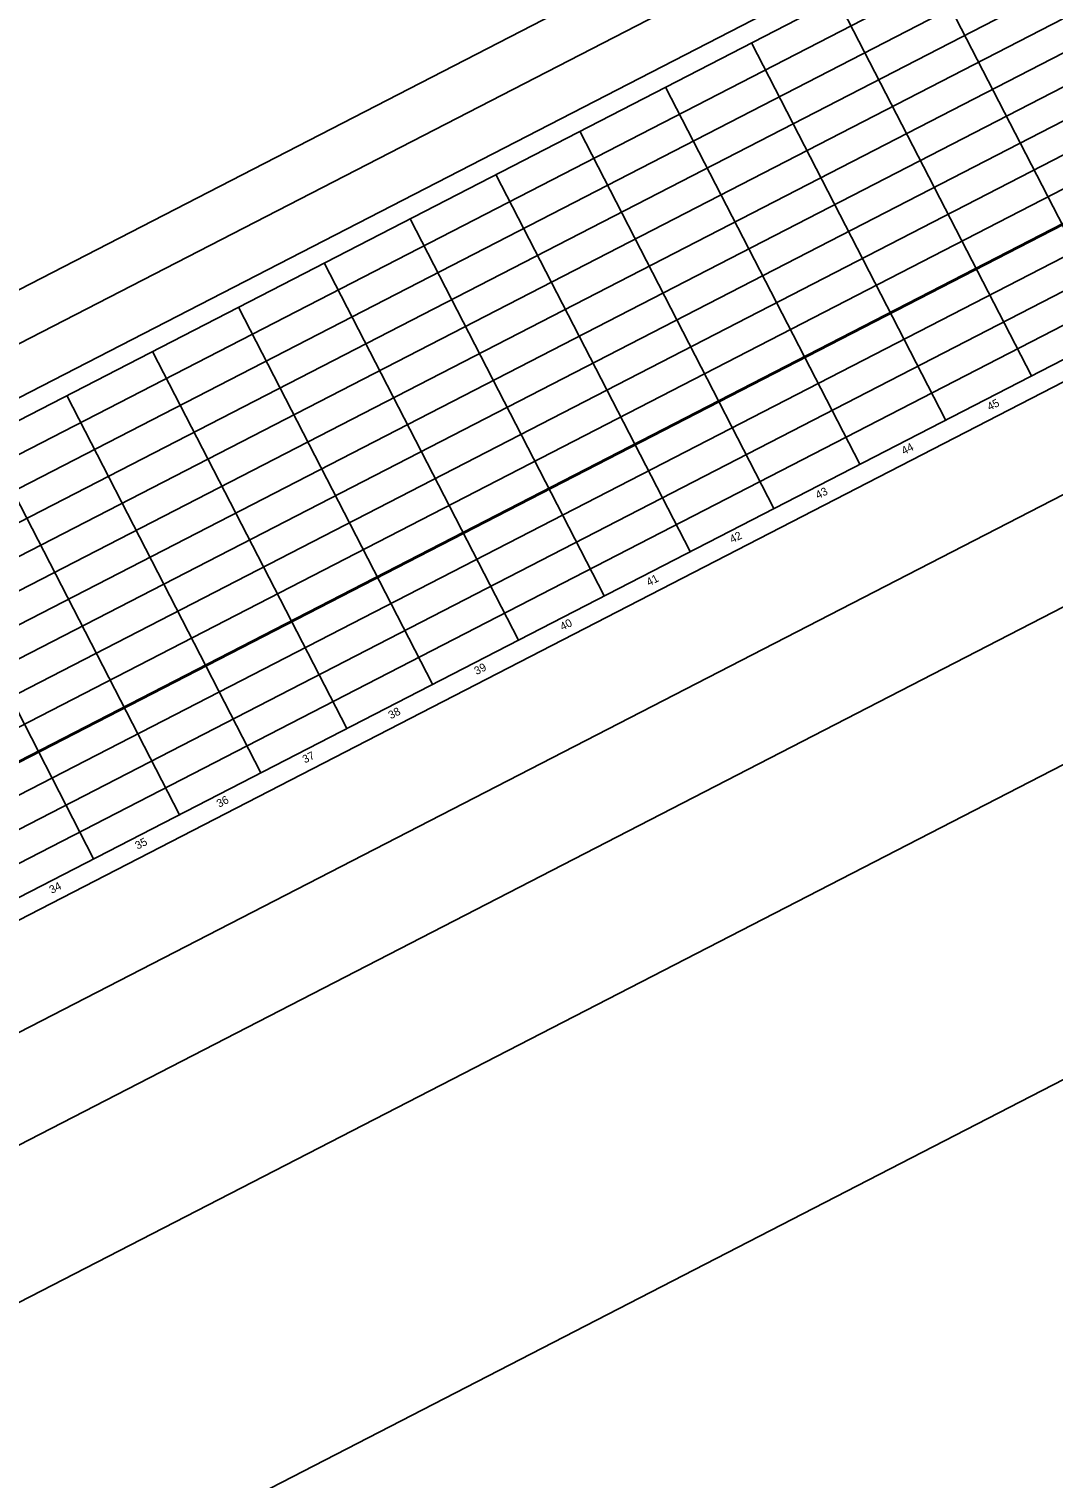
# Model space of a CAD drawing. Extents: x -886320 to -884760, y -1024172 to -1023483.
# Drawn here: x -885649.7 to -885521.7, y -1024061.4 to -1023880.4 of the extents above; entities that cross this region are included whole.
import ezdxf

# ---------------------------------------------------------------- set-up
doc = ezdxf.new("R2010")
doc.units = 0
for name, color, linetype in [('AGA__Netisknout', 7, 'Continuous'), ('Stavajici_betonova_draha', 7, 'Continuous'), ('Stavajici_betonova_draha_osa', 7, 'Continuous'), ('Stavajici_betonova_draha_Popis desky', 7, 'Continuous'), ('Stavajici_betonova_draha_Spára', 7, 'Continuous'), ('Stavajici_drahovy_system', 7, 'Continuous'), ('Stavajici_drahovy_system_osy', 7, 'Continuous'), ('Stavajici_drahovy_system_RWY_strip', 7, 'Continuous'), ('Stavajici_drahovy_system_TWY', 7, 'Continuous'), ('Stavajici_drahovy_system_TWY_osy', 7, 'Continuous')]:
    doc.layers.add(name, color=color, linetype=linetype)

msp = doc.modelspace()

# ---------------------------------------------------------------- linework, layer by layer
at = {"layer": 'AGA__Netisknout'}
msp.add_line((-886017.78, -1024147.99), (-884773.13, -1023507.02), dxfattribs=at)
at = {"layer": 'Stavajici_betonova_draha'}
for p, q in [((-886029.69, -1024124.32), (-884785.04, -1023483.35)), ((-886029.69, -1024124.32), (-884785.04, -1023483.35)), ((-886005.42, -1024171.44), (-884760.77, -1023530.47)), ((-886005.42, -1024171.44), (-884760.77, -1023530.47))]:
    msp.add_line(p, q, dxfattribs=at)
at = {"layer": 'Stavajici_betonova_draha_osa'}
msp.add_line((-886017.55, -1024147.88), (-884772.9, -1023506.91), dxfattribs=at)
at = {"layer": 'Stavajici_betonova_draha_Spára'}
for p, q in [((-886029.91, -1024124.43), (-884785.26, -1023483.46)), ((-886028.18, -1024127.8), (-884783.53, -1023486.82)), ((-886026.44, -1024131.16), (-884781.79, -1023490.19)), ((-886024.71, -1024134.53), (-884780.06, -1023493.56)), ((-886022.98, -1024137.89), (-884778.33, -1023496.92)), ((-886021.24, -1024141.26), (-884776.59, -1023500.29)), ((-886019.51, -1024144.63), (-884774.86, -1023503.65)), ((-886016.04, -1024151.36), (-884771.39, -1023510.39)), ((-886014.31, -1024154.72), (-884769.66, -1023513.75)), ((-886012.58, -1024158.09), (-884767.93, -1023517.12)), ((-886010.84, -1024161.46), (-884766.19, -1023520.48)), ((-886009.11, -1024164.82), (-884764.46, -1023523.85)), ((-886007.38, -1024168.19), (-884762.73, -1023527.21)), ((-886005.64, -1024171.55), (-884760.99, -1023530.58)), ((-885537.93, -1023871.07), (-885513.66, -1023918.19)), ((-885548.66, -1023876.6), (-885524.39, -1023923.72)), ((-885559.39, -1023882.12), (-885535.12, -1023929.24)), ((-885570.12, -1023887.65), (-885545.85, -1023934.77)), ((-885580.85, -1023893.17), (-885556.58, -1023940.3)), ((-885591.33, -1023898.57), (-885567.06, -1023945.69)), ((-885602.06, -1023904.1), (-885577.79, -1023951.22)), ((-885612.79, -1023909.62), (-885588.52, -1023956.74)), ((-885623.52, -1023915.15), (-885599.25, -1023962.27)), ((-885634.25, -1023920.67), (-885609.98, -1023967.79)), ((-885644.98, -1023926.2), (-885620.71, -1023973.32)), ((-885655.16, -1023931.44), (-885630.9, -1023978.57)), ((-885665.89, -1023936.97), (-885641.63, -1023984.09))]:
    msp.add_line(p, q, dxfattribs=at)
at = {"layer": 'Stavajici_drahovy_system'}
for p, q in [((-885721.56, -1024028.07), (-884864.53, -1023586.71)), ((-885726.12, -1024058.54), (-884837.08, -1023600.7)), ((-885744.78, -1024087.83), (-884802.4, -1023602.52)), ((-885728.75, -1024118.95), (-884786.38, -1023633.64))]:
    msp.add_line(p, q, dxfattribs=at)
at = {"layer": 'Stavajici_drahovy_system_osy'}
msp.add_line((-885731.84, -1024047.42), (-884842.81, -1023589.59), dxfattribs=at)
at = {"layer": 'Stavajici_drahovy_system_RWY_strip'}
for p, q in [((-885772.25, -1024034.49), (-884829.87, -1023549.18)), ((-884802.4, -1023602.52), (-885744.78, -1024087.83))]:
    msp.add_line(p, q, dxfattribs=at)
at = {"layer": 'Stavajici_drahovy_system_TWY'}
for p, q in [((-885887.27, -1024034.67), (-884885.91, -1023518.99)), ((-885748.12, -1023976.51), (-884891.09, -1023535.15))]:
    msp.add_line(p, q, dxfattribs=at)
at = {"layer": 'Stavajici_drahovy_system_TWY_osy'}
msp.add_line((-885886.7, -1024041.13), (-884883.17, -1023524.32), dxfattribs=at)

# ---------------------------------------------------------------- texts
at = {"layer": 'Stavajici_betonova_draha_Popis desky'}
for s, p in [('45', (-885529.62, -1023928.1)), ('44', (-885540.34, -1023933.62)), ('43', (-885551.07, -1023939.15)), ('42', (-885561.8, -1023944.67)), ('41', (-885572.21, -1023950.03)), ('40', (-885583.01, -1023955.59)), ('39', (-885593.74, -1023961.12)), ('38', (-885604.47, -1023966.65)), ('37', (-885615.2, -1023972.17)), ('36', (-885625.93, -1023977.7)), ('35', (-885636.12, -1023982.94)), ('34', (-885646.85, -1023988.47))]:
    msp.add_text(s, height=1, rotation=27.2477, dxfattribs=at).set_placement(p)

doc.saveas('drawing.dxf')
